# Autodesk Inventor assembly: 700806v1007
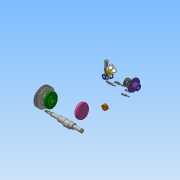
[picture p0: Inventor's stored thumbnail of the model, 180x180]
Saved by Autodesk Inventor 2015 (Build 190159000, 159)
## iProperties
Created: 2020-08
Part Number: 700806v1007
Document SubType Name: Assembly
Designer: user
Author: user
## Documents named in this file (18)
- C:\Users\user\Desktop\700806v1007\700806v1007.iam
- C:\Users\user\Desktop\700806v1007\본체.ipt
- C:\Users\user\Desktop\700806v1007\V-벨트풀리.ipt
- C:\Users\user\Desktop\700806v1007\너트 M8.ipt
- C:\Users\user\Desktop\700806v1007\뒤커버.ipt
- C:\Users\user\Desktop\700806v1007\멈춤링 15x1.ipt
- C:\Users\user\Desktop\700806v1007\멈춤링 35x1.6.ipt
- 멈춤링 35x1.6.ipt
- C:\Users\user\Desktop\700806v1007\베어링 6202.ipt
- 베어링 6202.ipt
- C:\Users\user\Desktop\700806v1007\볼트 M4.ipt
- C:\Users\user\Desktop\700806v1007\상부커버.ipt
- C:\Users\user\Desktop\700806v1007\슬라이드.ipt
- C:\Users\user\Desktop\700806v1007\앞커버.ipt
- C:\Users\user\Desktop\700806v1007\오일 실 15 30 7.ipt
- C:\Users\user\Desktop\700806v1007\칼라.ipt
- C:\Users\user\Desktop\700806v1007\키 3x3x12.ipt
- C:\Users\user\Desktop\700806v1007\편심축.ipt
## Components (1 placed, 1 different names)
1. V-벨트풀리:1
